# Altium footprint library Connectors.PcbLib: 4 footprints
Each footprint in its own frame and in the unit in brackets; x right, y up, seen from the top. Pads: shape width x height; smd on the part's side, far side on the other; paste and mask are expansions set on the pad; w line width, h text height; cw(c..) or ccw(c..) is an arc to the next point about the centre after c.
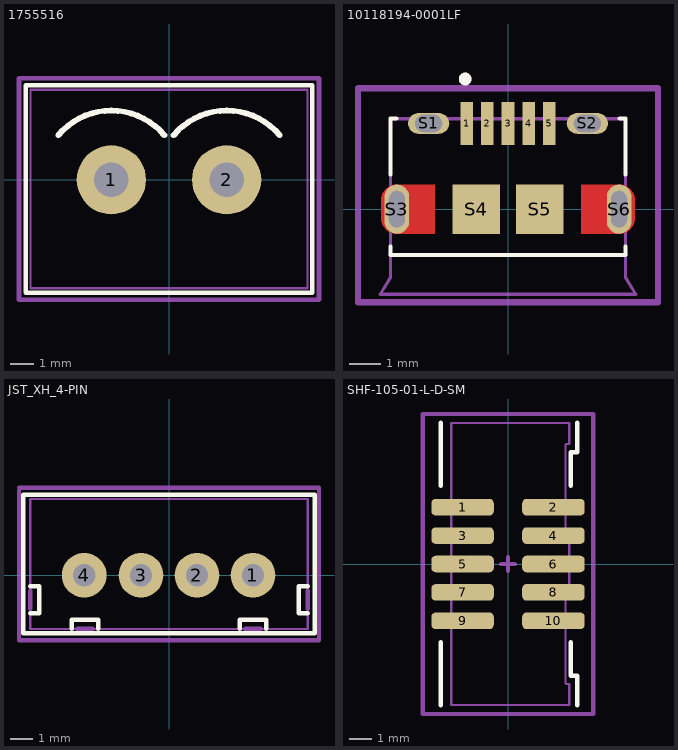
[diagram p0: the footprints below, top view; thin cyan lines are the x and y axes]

## 1755516 [mm] "Pin header, straight, Straight, 5mm Pitch, 2 Poles, Phoenix Contact"
height 12
pads (2):
  round 3 hole 1.5: 1(-2.5,0) 2(2.5,0)
Top Overlay:
  lines w0.2: -6.2,-4.9 6.2,-4.9 6.2,4.1 -6.2,4.1 -6.2,-4.9
  lines w0.254: -4.799,1.929 cw(c-2.5,0) -0.201,1.929 ; 0.201,1.929 cw(c2.5,0) 4.799,1.929
Mechanical 13:
  lines w0.1: -6,-4.7 -6,3.9 6,3.9 6,-4.7 -6,-4.7
Mechanical 15:
  lines w0.2: -6.5,-5.2 -3.3,-5.2 6.5,-5.2 6.5,4.4 -6.5,4.4 -6.5,-5.2
3D body "1755516.stp": height 12, standoff -3.9, extent -6,-4.72 6,3.88

## 10118194-0001LF [mm] "Micro USB, Input Output Connectors, B TYPE RECEPTACLE with flange"
pads (11):
  rect 0.4x1.35 smd: 1(-1.3,2.7) 2(-0.65,2.7) 3(0,2.7) 4(0.65,2.7) 5(1.3,2.7)
  oval 1.3x0.65 hole 0.55 slot 0.85 at 0 deg: S1(-2.5,2.7) S2(2.5,2.7)
  oval 0.775x1.55 hole 0.5 slot 1.15 at 90 deg: S3(-3.5,0) S6(3.5,0)
  rect 1.5x1.55 smd: S4(-1,0) S5(1,0)
Top Layer:
  region: 192 vertices and 0 holes, not listed, extent 2.3,-0.78 4,0.775
  region: 192 vertices and 0 holes, not listed, extent -4,-0.775 -2.3,0.78
Top Overlay:
  circle w0.2: c-1.35,4.1 r0.1
  lines w0.127: -3.7,-1.18 -3.7,-1.45 3.7,-1.45 3.7,-1.18 ; -3.7,1.095 -3.7,2.85 -3.52,2.85 ; 3.52,2.85 3.7,2.85 3.7,1.095
Top Paste:
  drawing of 6 lines, arcs and shapes, not listed
Top Solder:
  region: 3.626,0.874 3.652,0.872 3.678,0.869 3.704,0.864 3.729,0.858 3.755,0.851 3.779,0.842 3.803,0.832 3.827,0.821 3.85,0.808 3.872,0.794 3.894,0.78 3.915,0.764 3.935,0.747 3.954,0.729 3.972,0.71 3.989,0.69 4.005,0.669 4.019,0.647 4.033,0.625 4.046,0.602 4.057,0.578 4.067,0.554 4.076,0.53 4.083,0.504 4.089,0.479 4.094,0.453 4.097,0.427 4.099,0.401 4.1,0.375 4.1,-0.375 4.099,-0.401 4.097,-0.427 4.094,-0.453 4.089,-0.479 4.083,-0.504 4.076,-0.53 4.067,-0.554 4.057,-0.578 4.046,-0.602 4.033,-0.625 4.019,-0.647 4.005,-0.669 3.989,-0.69 3.972,-0.71 3.954,-0.729 3.935,-0.747 3.915,-0.764 3.894,-0.78 3.872,-0.794 3.85,-0.808 3.827,-0.821 3.803,-0.832 3.779,-0.842 3.755,-0.851 3.729,-0.858 3.704,-0.864 3.678,-0.869 3.652,-0.872 3.626,-0.874 3.6,-0.875 2.2,-0.875 2.2,0.875 3.6,0.875
  region: -2.2,-0.875 -3.6,-0.875 -3.626,-0.874 -3.652,-0.872 -3.678,-0.869 -3.704,-0.864 -3.729,-0.858 -3.755,-0.851 -3.779,-0.842 -3.803,-0.832 -3.827,-0.821 -3.85,-0.808 -3.872,-0.794 -3.894,-0.78 -3.915,-0.764 -3.935,-0.747 -3.954,-0.729 -3.972,-0.71 -3.989,-0.69 -4.005,-0.669 -4.019,-0.647 -4.033,-0.625 -4.046,-0.602 -4.057,-0.578 -4.067,-0.554 -4.076,-0.53 -4.083,-0.504 -4.089,-0.479 -4.094,-0.453 -4.097,-0.427 -4.099,-0.401 -4.1,-0.375 -4.1,0.375 -4.099,0.401 -4.097,0.427 -4.094,0.453 -4.089,0.479 -4.083,0.504 -4.076,0.53 -4.067,0.554 -4.057,0.578 -4.046,0.602 -4.033,0.625 -4.019,0.647 -4.005,0.669 -3.989,0.69 -3.972,0.71 -3.954,0.729 -3.935,0.747 -3.915,0.764 -3.894,0.78 -3.872,0.794 -3.85,0.808 -3.827,0.821 -3.803,0.832 -3.779,0.842 -3.755,0.851 -3.729,0.858 -3.704,0.864 -3.678,0.869 -3.652,0.872 -3.626,0.874 -3.6,0.875 -2.2,0.875
Mechanical 13:
  circle w0.2: c-1.35,4.1 r0.1
  lines w0.1: -4.025,-2.68 4.025,-2.68 3.7,-2.15 3.7,-1.45 3.7,2.85 -3.7,2.85 -3.7,-1.45 -3.7,-2.15 -4.025,-2.68
Mechanical 15:
  lines w0.127: -3.7,-1.45 3.7,-1.45
  lines w0.2: -4.725,-2.93 -4.725,3.81 4.725,3.81 4.725,-2.93 -4.725,-2.93
3D body "10118194-0001LF--3DModel-STEP-533217.STEP": height 3.12, standoff -0.15, extent -4.025,-2.73 4.025,2.85

## JST_XH_4-PIN [mm] "JST XH 4 pin connector"
height 7
pads (4):
  round 2 hole 1: 1(3.75,0) 2(1.25,0) 3(-1.25,0) 4(-3.79,0)
Top Overlay:
  lines w0.2: -6.2,-1.7 -5.8,-1.7 -5.8,-0.5 -6.2,-0.5 ; -4.35,-2.4 -4.35,-2 -3.15,-2 -3.15,-2.4 ; 3.15,-2.4 3.15,-2 4.35,-2 4.35,-2.4 ; 6.2,-1.7 5.8,-1.7 5.8,-0.5 6.2,-0.5 ; -6.5,-2.6 6.5,-2.6 6.5,3.6 -6.5,3.6 -6.5,-2.6 ; -6.5,-2.6 -6.5,-2.6
Mechanical 13:
  lines w0.1: -6.2,-2.4 6.2,-2.4 6.2,3.4 -6.2,3.4 -6.2,-2.4
  lines w0.2: -6.2,-1.5 -6.2,-0.7 ; -4.1,-2.4 -3.4,-2.4 ; 3.4,-2.4 4.1,-2.4 ; 6.2,-1.5 6.2,-0.7
Mechanical 15:
  lines w0.2: -6.7,3.8 -6.7,-2.9 6.7,-2.9 6.7,3.9 -6.7,3.9
3D body "JST XH 4 B4B-XH-A.STEP": height 7, standoff -3.45, extent -6.2,-2.375 6.2,3.375

## SHF-105-01-L-D-SM [mm]
pads (10):
  rrect50% 2.79x0.74 smd: 1(-2.03,2.54) 2(2.03,2.54) 3(-2.03,1.27) 4(2.03,1.27) 5(-2.03,0) 6(2.03,0) 7(-2.03,-1.27) 8(2.03,-1.27) 9(-2.03,-2.54) 10(2.03,-2.54)
Top Overlay:
  lines w0.2: -3,-6.3 -3,-3.5 ; -3,3.5 -3,6.3 ; 2.8,-3.5 2.8,-5 3.1,-5 3.1,-6.3 ; 2.8,3.5 2.8,5 3.1,5 3.1,6.3
Mechanical 13:
  lines w0.1: -2.54,-6.3 2.74,-6.3 2.74,-5.36 2.6,-5.36 2.57,-5.33 2.57,-1.27 2.74,-1.27 2.74,1.27 2.57,1.27 2.57,5.33 2.6,5.36 2.74,5.36 2.74,6.3 -2.54,6.3 -2.54,-6.3
Mechanical 15:
  lines w0.2: -0.3,0 0.3,0 ; 0,-0.3 0,0.3 ; -3.8,-6.7 -3.8,6.7 3.8,6.7 3.8,-6.7 -3.8,-6.7
3D body "SHF-105-01-L-D-SM.stp": height 5.33, standoff -0.13, extent -3.048,-6.35 3.048,6.35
